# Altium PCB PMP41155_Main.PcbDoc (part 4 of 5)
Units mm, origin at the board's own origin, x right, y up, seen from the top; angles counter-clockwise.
Board outline 74 x 146.5 mm, 8 copper layers (Top Layer, Signal Layer 1, Signal Layer 2, Signal Layer 3, Signal Layer 4, Signal Layer 5, Signal Layer 6, Bottom Layer), stack 1.534 mm thick; 249 components, 190 nets, 902 pads, 747 vias.
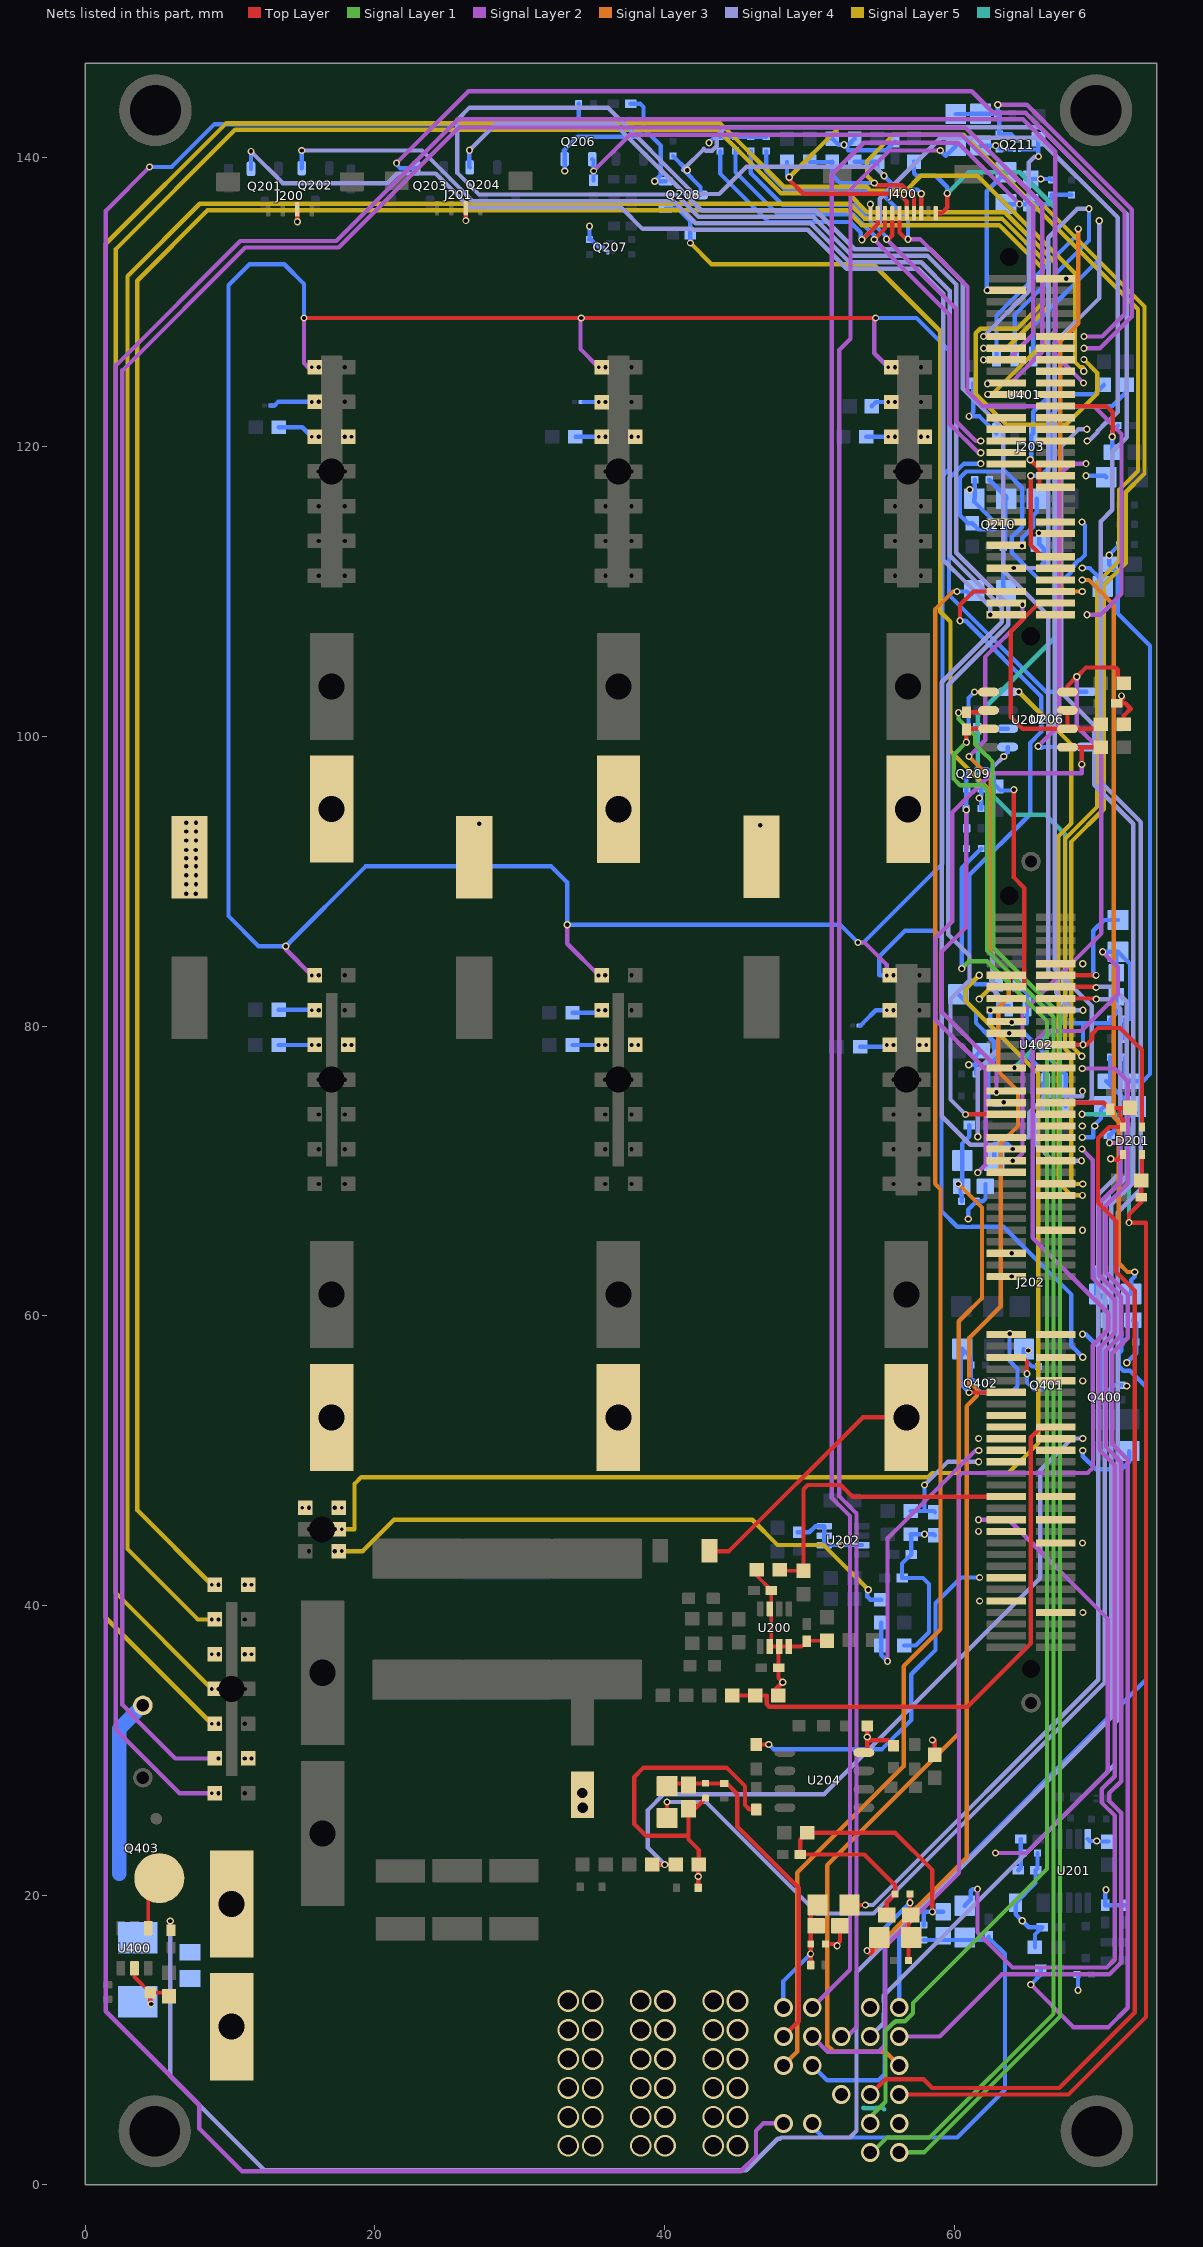
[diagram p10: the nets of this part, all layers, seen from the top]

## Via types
v1: diameter 0.5, hole 0.3, Top Layer to Bottom Layer, 533 vias
v2: diameter 0.508, hole 0.254, Top Layer to Bottom Layer, tented both sides, 102 vias
v3: diameter 1.5, hole 1.2, Top Layer to Bottom Layer, 72 vias
v4: diameter 1.3, hole 0.9, Top Layer to Bottom Layer, 30 vias
v5: diameter 1.27, hole 0.711, Top Layer to Bottom Layer, 6 vias
v6: diameter 1, hole 0.5, Top Layer to Bottom Layer, 2 vias
v7: diameter 2.49, hole 2.49, Top Layer to Bottom Layer, 2 vias

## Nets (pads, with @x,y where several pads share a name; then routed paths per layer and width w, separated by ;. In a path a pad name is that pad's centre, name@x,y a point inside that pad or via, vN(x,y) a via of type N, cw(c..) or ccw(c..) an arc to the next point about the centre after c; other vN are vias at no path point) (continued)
SGND: C202.2 C203.1 C204.2 C205.2 C206.2 C207.2 C208.2 C209.1 C210.2 C212.2 C213.2 C214.2 C215.2 C216.2 C217.2 C218.2 C219.1 C220.2 C221.1 C223.2 C224.2 C225.2 C226.2 C227.2 C228.2 C229.2 C230.1 C231.2 C232.1 C233.2 C234.1 C235.1 C236.1 C300.2 C301.2 C302.2 C306.2 C307.2 C400.1 C401.1 C402.1 C403.1 C404.2 C405.2 C406.2 C407.2 C408.2 C409.2 C410.2 C411.2 C412.2 C413.2 C414.2 C415.2 C416.2 C417.2 C418.2 C419.2 C420.2 C421.1 C422.1 C423.1 C424.1 C425.1 C426.1 D201.1 D201.4 D400.2 J200.2 J201.2 J202.7 J202.10 J202.19 J202.22 J202.35 J202.38 J202.46 J202.47 J202.65 J202.83 J202.97 J202.111 J203.135 J203.157 J203.179 J400.10 pad.1@9.21,36.64 pad.1@11.01,29.44 pad.1@11.01,36.64 pad.1@11.01,41.44 pad.1@15.46,46.76 pad.1@16.12,78.71 pad.1@16.12,120.71 pad.1@17.24,46.76 pad.1@17.92,78.71 pad.1@17.92,120.71 pad.1@35.92,78.71 pad.1@35.924,120.703 pad.1@37.72,78.71 pad.1@37.724,120.703 pad.1@55.81,78.71 pad.1@55.918,120.705 pad.1@57.61,78.71 pad.1@57.718,120.705 pad.2@10.11,10.92 pad.2@17.02,52.99 pad.2@17.02,94.99 pad.2@36.82,52.99 pad.2@36.824,94.983 pad.2@56.71,52.99 pad.2@56.818,94.985 Q206.2 Q207.2 Q208.2 Q209.2 Q210.2 Q211.2 Q400.2 Q401.2 Q402.2 R200.1 R209.1 R216.1 R217.1 R227.1 R228.1 R229.1 R230.2 R247.1 R256.1 R261.1 R267.1 R269.1 R401.1 R403.1 R405.1 R418.1 R419.1 R420.1 R421.1 R430.1 R431.1 R432.1 R443.1 R444.1 R445.1 R456.1 R457.1 R458.1 R459.1 U200.2 U200.3 U200.4 U200.7 U201.8 U202.2 U202.3 U202.4 U202.7 U204.4 U206.2 U207.5 U400.2 U401.4 U402.4 | length 294.5
  Top Layer w0.254: U400.2@3.405,14.96 3.405,14.345 C403.1@4.49,13.26 5.567,13.26 C405.2@5.796,13.031 ; C208.2@46.373,42.468 46.373,42.052 C204.2@47.382,41.043 47.382,37.273 U200.2@47.278,37.168 U200.3@47.928,37.168 ; C205.2@47.878,35.71 47.878,37.118 U200.3@47.928,37.168 ; C206.2@51.221,37.577 49.885,37.577 C207.2@49.83,37.523 49.475,37.168 U200.4@48.578,37.168 U200.3@47.928,37.168
  Top Layer w0.3: C403.1@4.49,13.26 4.49,12.547 v1(4.553,12.485) ; J200.2@14.647,136.406 14.652,136.401 v1(14.652,135.544) ; v1(26.288,135.63) J201.2@26.288,136.454 ; R230.2@42.328,20.511 v1(42.328,21.286) 42.328,22.061 R229.1@42.378,22.111 42.378,23.124 41.658,23.844 41.658,24.1 ; R430.1@42.841,26.7 42.097,25.957 C412.2@41.658,25.957 41.658,24.1 ; C307.2@43.11,43.78 43.13,43.76 44.46,43.76 53.69,52.99 pad.2@56.71,52.99 ; C235.1@46.34,25.914 45.86,25.914 45.86,25.935 45.565,26.23 45.565,27.532 44.288,28.809 38.554,28.809 37.91,28.165 37.91,24.911 38.721,24.1 41.658,24.1 ; R228.1@47.86,33.79 47.61,34.04 47.61,34.15 v1(48.17,34.71) 47.878,35.002 C205.2@47.878,35.71 ; R418.1@51.124,16.631 51.889,16.631 v1@51.92,16.6 ; v1(51.92,16.503) v1@51.92,16.6 ; C407.2@52.117,17.886 52.117,16.797 v1@51.92,16.6 ; U204.4@53.765,29.849 54.01,30.094 v1(54.01,30.919) C221.1@54.01,31.694 ; v1@54.01,30.687 55.447,30.687 C236.1@55.825,30.309 ; C418.2@55.306,18.592 C418.2@55.35,18.636 55.35,19.499 R456.1@55.931,20.08 55.931,20.661 53.788,22.804 C218.2@49.37,22.804 49.37,23.824 C217.2@49.86,24.314 55.926,24.314 58.5,21.74 v1(58.5,18.846) ; C220.2@58.66,29.694 v1@58.66,30.69 ; v1(61.037,54.705) 63.585,54.705 J202.46@63.6,54.72 ; v1(61.405,103.077) U207.5@62.38,103.077 ; v1(65.861,114.058) 66.962,114.058 J203.135@67,114.02 ; J202.97@67,78.72 v1(68.9,78.72) 69.114,78.72 69.124,78.71 69.541,79.127 69.541,79.484 69.93,79.874 71.462,79.874 72.97,78.365 D201.1@72.97,73.04 ; J203.157@67,122.82 70.53,122.82 70.96,122.39 70.96,120.741 v1(70.924,120.705) ; v1(70.82,70.851) 70.92,70.851 70.987,70.783 71.313,70.783 D201.4@71.67,71.14 ; C233.2@71.23,102.3 C233.2@71.563,102.3 ; v1(71.563,102.81) 71.683,102.69 71.563,102.57 C233.2@71.563,102.3 ; R267.1@71.722,100.857 71.722,101.452 72.192,101.922 71.814,102.3 C233.2@71.563,102.3
  Signal Layer 6 w0.3: 53.709,5.322 53.788,5.322 53.818,5.293 54.602,5.293 54.632,5.322 55.068,5.322 55.18,5.21
  Bottom Layer w0.3: C223.2@13.35,78.709 pad.1@15.649,78.709 ; C228.2@13.375,121.366 14.994,121.366 v2(15.65,120.71) ; v1(33.113,139.057) 33.108,139.063 Q206.2@33.108,139.877 33.108,140.41 33.05,140.467 34.013,141.43 37.979,141.43 38.552,142.003 ; C225.2@33.65,78.71 v2(35.45,78.71) ; C227.2@33.854,120.703 v2(35.454,120.703) ; v1(34.823,135.247) 34.823,134.325 R247.1@34.817,134.32 34.93,134.32 35.442,133.807 35.737,133.807 35.894,133.65 35.909,133.65 Q207.2@36.037,133.523 ; C224.2@37.67,143.707 38.32,143.707 38.552,143.475 38.552,142.003 ; Q208.2@40.09,138.35 v1(39.326,138.35) 39.748,138.772 39.748,140.807 38.552,142.003 ; v1(43.07,141.01) 43.49,141.43 C422.1@43.84,141.43 C421.1@45.96,141.43 C424.1@47.02,141.43 ; C213.2@49.188,45.053 49.995,45.053 50.42,45.478 U202.4@51.038,45.478 U202.3@51.038,44.828 U202.2@51.038,44.178 U202.7@53.638,44.178 ; C425.1@51.585,141.29 52.009,140.866 v1(52.401,140.866) ; C426.1@53.145,141.29 52.721,140.866 v1(52.401,140.866) ; C226.2@53.51,78.58 55.21,78.58 v2(55.34,78.71) ; C229.2@53.945,120.703 55.155,120.703 ; R459.1@55.918,141.09 55.318,140.49 52.67,140.49 52.67,140.597 v1(52.401,140.866) ; R227.1@56.558,37.235 57.345,37.235 58.27,38.16 58.27,41.49 57.856,41.904 C212.2@56.405,41.904 56.405,42.898 C215.2@57.035,43.528 57.035,44.898 C214.2@57.005,44.928 58.6,44.928 C216.2@58.675,44.853 ; R457.1@57.901,17.932 57.901,18.701 58.046,18.846 v1(58.5,18.846) C419.2@59.26,18.846 ; R405.1@60.45,57.328 60.45,55.291 v1(61.037,54.705) ; R405.1@60.57,57.328 R405.1@60.57,57.72 ; R405.1@60.72,57.57 R405.1@60.57,57.72 ; v1(60.98,66.69) 60.98,67.348 R445.1@61.542,67.91 61.98,67.91 62.168,68.098 C417.2@62.168,69.11 ; v1(61.01,77.335) 61.515,77.335 ; 61.315,55.57 61.268,55.57 61.17,55.667 C402.1@61.17,56.608 61.17,57.12 R405.1@60.57,57.72 ; C406.2@61.328,124.39 61.328,122.41 v1(61.027,122.11) 61.756,122.11 U401.4@62.926,120.94 ; v1(61.405,103.077) 60.993,102.665 60.993,100.555 C231.2@61.59,100.555 61.595,100.55 U206.2@63.695,100.55 ; C232.1@61.42,117.74 61.42,116.44 R261.1@61.4,116.42 61.4,116.204 Q210.2@62.753,114.851 ; R420.1@61.515,76.71 61.515,77.335 ; Q209.2@61.664,97.211 61.664,97.076 61.88,96.86 61.88,95.905 v1(61.73,95.755) 61.88,95.605 61.88,95.057 R256.1@61.852,95.03 ; R269.1@61.83,140.81 v1(62.871,140.81) 62.901,140.81 C234.1@63.121,140.59 63.171,140.54 64.01,140.54 ; C409.2@61.84,78.31 61.515,77.985 61.515,77.335 ; R403.1@64.82,57.71 64.82,57.065 65.38,56.505 C401.1@65.83,56.505 65.83,55.74 66.04,55.53 ; C414.2@65.3,138.5 v1(65.988,138.5) 66.676,138.5 R432.1@66.736,138.44 ; R209.1@65.584,16.405 65.584,17.283 C210.2@66.079,17.779 65.151,17.779 64.255,18.674 C203.1@64.255,19.475 65.624,20.844 R217.1@65.624,21.715 65.754,21.845 C219.1@65.754,22.905 ; v1@65.884,114.058 C416.2@65.884,113.29 66.198,112.977 R444.1@66.198,111.777 ; C411.2@67.681,82.865 67.681,81.476 U402.4@67.575,81.37 67.575,80.21 68.8,80.21 ; C209.1@68.49,14.53 68.55,14.47 v1(68.55,13.43) ; v1(68.89,50.71) 68.89,50.315 69.785,49.42 71.58,49.42 72.087,49.927 R401.1@72.087,50.665 ; v1@68.901,78.721 68.901,80.11 68.8,80.21 ; U201.8@69.239,23.875 69.409,23.705 69.448,23.745 v1(69.856,23.745) 69.896,23.705 C202.2@70.634,23.705 ; v1@70.524,20.42 v1(70.484,20.38) 70.444,20.34 R200.1@70.444,19.312 R216.1@71.804,19.312 R216.1@71.947,19.312 ; 70.688,54.864 71.03,55.205 C400.1@71.574,55.205 ; C408.2@70.924,119.64 v1(70.924,120.705) 70.924,121.087 R419.1@71.318,121.48 ; C415.2@71.205,82.039 71.205,80.9 R443.1@70.804,80.499 70.804,80.21 68.8,80.21 ; R431.1@71.428,113.26 70.704,112.537 C413.2@70.704,111.897 71.3,111.301 71.3,108.5 73.53,106.27 73.53,76.701 73.037,76.208 C410.2@72.167,76.208 71.81,76.564 R421.1@71.81,77.859 ; v1(71.916,56.759) 72.573,57.415 72.573,59.487 C420.2@72.35,59.71
  other v1: 64.703,18.226 58.5,30.72 68.894,39.523 61.76,40.31 52.198,44.178 68.87,44.32 57.95,44.928 61.68,45.119 61.69,51.529 71.915,55.16 68.88,55.51 65.13,57.61 68.87,65.92 68.841,73.107 68.89,84.32 6.98,89.146 7.64,89.146 6.98,89.806 7.65,89.806 6.98,90.426 7.65,90.426 6.98,91.036 7.65,91.036 6.99,91.59 7.65,91.59 6.98,92.17 7.64,92.17 6.98,92.83 7.65,92.83 6.98,93.45 7.65,93.45 46.61,93.87 27.21,93.99 6.98,94.06 7.65,94.06 70.713,112.529 61.079,117.038 67.74,131.62 54.221,136.761
  other v2: 11.48,29.44 8.74,36.64 11.48,36.64 11.49,41.44 14.98,46.76 17.72,46.76 15.65,78.71 18.39,78.71 38.19,78.71 58.08,78.71 38.194,120.703 18.39,120.71 55.448,120.705 58.188,120.705
  other v3: 33.36,2.69 35.04,2.69 38.36,2.69 40.04,2.69 43.36,2.69 45.04,2.69 33.36,4.69 35.04,4.69 38.36,4.69 40.04,4.69 43.36,4.69 45.04,4.69 33.36,6.69 35.04,6.69 38.36,6.69 40.04,6.69 43.36,6.69 45.04,6.69 33.36,8.69 35.04,8.69 38.36,8.69 40.04,8.69 43.36,8.69 45.04,8.69 33.36,10.69 35.04,10.69 38.36,10.69 40.04,10.69 43.36,10.69 45.04,10.69 33.36,12.69 35.04,12.69 38.36,12.69 40.04,12.69 43.36,12.69 45.04,12.69
  other v4: 56.21,4.24 52.21,6.24 54.21,12.24
  other v5: 34.35,26.04 34.32,27.05
SHELF_ADDR0: C407.1 R408.1 R414.2 R418.2 | length 8.8
  Top Layer w0.3: R408.1@50.101,15.181 50.101,18.856 R414.2@50.571,19.326
  Bottom Layer w0.3: v4(48.21,12.24) 48.21,14.064 v1(50.09,15.944)
SHELF_ADDR1: C412.1 R422.1 R425.2 R430.2 | length 24.2
  Top Layer w0.3: R425.2@40.178,27.532 40.353,27.708 42.841,27.708 R422.1@44.139,27.708 44.314,27.708 45.03,26.991 45.03,24.744 49.263,20.512 49.263,12.632 49.263,11.953 49.263,11.293 v4(48.21,10.24)
SHELF_ADDR2: C415.1 R437.1 R440.2 R443.2 | length 108.3
  Signal Layer 2 w0.3: v4(50.21,10.24) 51.26,9.19 54.8,9.19 55.25,9.64 55.25,16.457 60.334,21.54 60.334,48.931 60.551,49.148 62.752,49.148 69.218,49.148 69.589,49.519 69.589,54.181 69.578,54.192 69.578,56.128 69.58,56.13 69.58,57.978 70.643,59.041 70.643,60.178 65.435,65.386 65.435,72.04 65.435,78.769 66.336,79.67 68.78,79.67 71.29,82.18 71.29,84.105 v1(70.255,85.14)
  Bottom Layer w0.3: v1(70.255,85.14) R440.2@71.32,85.14 ; C415.1@71.205,83.691 71.205,85.025 R440.2@71.32,85.14 ; R437.1@71.79,79.16 R443.2@71.79,80.499 ; R443.2@71.829,80.499 72.168,80.499 72.168,84.292 72.014,84.446 R440.2@71.32,85.14
SHELF_ADDR3: C420.1 R451.1 R455.2 R458.2 | length 59.7
  Bottom Layer w0.3: v4(56.21,12.24) 56.21,17.83 57.354,18.974 57.354,19.073 57.675,19.393 57.773,19.393 73.25,34.87 73.25,55.104 72.143,56.211 71.69,56.211 71.369,56.532 71.369,57.417 71.535,57.583 R458.2@71.535,58.19 71.535,58.873 C420.1@70.698,59.71 ; R455.2@69.805,61.51 R451.1@69.805,63.185 ; R455.2@70.03,61.51 70.454,61.086 C420.1@70.454,59.71
SYS_AC_LOSS_1: C419.1 R450.1 R454.2 R457.2 | length 35.1
  Bottom Layer w0.3: v4(50.21,4.24) 50.21,4.03 50.97,3.27 60.21,3.27 63.51,6.57 63.51,15.95 62.553,16.907 R457.2@57.901,16.907 59.26,16.907 60.731,16.907 62.169,16.907 R450.1@62.381,17.12
SYS_AC_LOSS_2: C417.1 R438.1 R442.2 R445.2 | length 76.1
  Signal Layer 3 w0.3: v4(56.21,8.24) 55.25,9.2 51.686,9.2 51.579,9.308 51.23,9.657 51.23,22.069 60.323,31.163 60.323,59.624 61.925,61.226 61.925,67.479 v1(60.295,69.11)
  Bottom Layer w0.3: v1(60.295,69.11) 60.295,68.95 C417.1@60.514,68.95 ; R445.2@60.517,67.91 60.517,68.34 60.436,68.421 60.436,68.872 C417.1@60.514,68.95 ; R438.1@61.037,73.18 61.037,72.367 60.567,71.897 R442.2@60.567,70.72 60.567,69.003 C417.1@60.514,68.95
SYS_BBU_ALERT: Q206.3 R239.1 | length 215.7
  Signal Layer 2 w0.3: v1@4.55,139.43 1.42,136.3 1.42,11.98 7.872,5.528 7.872,3.888 10.825,0.935 45.265,0.935 46.32,1.99 46.32,3.739 46.821,4.24 v4(48.21,4.24)
  Bottom Layer w0.3: v1(4.446,139.326) 5.966,139.326 8.935,142.295 34.075,142.295 R239.1@34.075,143.707
SYS_BBU_RESET: C418.1 R452.1 R453.2 R456.2 | length 22.8
  Top Layer w0.3: R452.1@56.848,15.491 C418.1@56.848,18.636 ; R456.2@56.956,20.08 56.956,18.681 C418.1@57.001,18.636
  Bottom Layer w0.3: v4(50.21,8.24) 51.23,7.22 54.8,7.22 55.21,7.63 55.21,17.725 v1(56.955,19.47)
SYS_PLS_LOP: Q208.3 R246.1 | length 174.1
  Signal Layer 4 w0.3: 41.29,139.15 42.723,140.583 42.843,140.463 43.297,140.463 43.617,140.783 43.617,141.237 43.497,141.357 44.22,142.08 65.937,142.08 71.93,136.087 71.93,120.67 70.924,119.664 70.924,115.664 70.12,114.86 70.12,96.857 72.88,94.097 72.88,68.743 71.299,67.162 71.299,32.087 71.11,31.897 71.11,29.045 55.142,13.078 55.142,12.647 55.157,12.632 55.157,11.848 55.142,11.833 55.142,11.172 v4(54.21,10.24)
  Bottom Layer w0.3: R246.1@40.59,140.085 41.568,139.107 v1(41.58,139.107) ; 41.29,139.15 42.49,137.95 Q208.3@42.49,137.4
SYS_Present_L: C414.1 R424.1 R427.2 R432.2 | length 149
  Signal Layer 2 w0.3: v4(50.21,12.24) 52.815,14.845 52.815,46.177 51.54,47.453 51.54,138.79 53.76,141.01 58.819,141.01 58.823,141.015 59.277,141.015 59.281,141.01 60.27,141.01 v1(64.51,136.77)
  Bottom Layer w0.3: R427.2@63.575,136.77 C414.1@65.3,136.77 ; C414.1@65.3,136.848 65.742,136.848 65.829,136.761 66.649,136.761 66.736,136.848 R432.2@66.736,137.415 68.093,137.415 R424.1@68.11,137.398
SYS_PULSE_MGMT_1: C410.1 R411.1 R417.2 R421.2 | length 84.7
  Signal Layer 2 w0.3: v4(56.21,10.24) 59.005,10.24 63.295,14.53 70.714,14.53 71.538,15.354 71.538,25.298 71.538,25.678 71.062,26.154 70.714,26.502 70.714,27.047 71.538,27.871 71.538,49.889 70.483,50.944 70.483,54.552 70.473,54.563 70.473,55.757 70.474,55.759 70.474,57.607 71.538,58.671 71.538,61.291 70.025,62.804 70.025,67.786 71.468,69.229 71.468,71.953 v1(70.726,71.953)
  Bottom Layer w0.3: C410.1@70.515,76.208 R417.2@72.225,74.498 ; R411.1@70.69,72.413 R411.1@70.716,72.439 ; R411.1@70.716,72.503 R411.1@70.716,72.439 ; v1(70.726,71.953) 70.716,71.963 R411.1@70.716,72.439 ; C410.1@70.785,76.208 R421.2@70.785,77.859 ; R417.2@72.56,74.033 72.31,74.033 R411.1@70.716,72.439
SYS_RS485+: R264.2 U207.6 | length 110.1
  Top Layer w0.3: v1(60.3,101.65) 60.81,101.65 R264.2@60.85,101.69 62.263,101.69 U207.6@62.38,101.807
  Signal Layer 1 w0.3: v4(56.21,2.24) 57.926,2.24 67.312,11.626 67.312,80.828 62.723,85.417 62.723,95.342 62.725,95.343 62.725,96.167 62.723,96.168 62.723,96.515 62.65,96.588 62.65,98.283 62.262,98.671 62.246,98.671 61.925,98.992 61.445,99.472 61.445,100.071 60.3,101.216 v1(60.3,101.65)
SYS_RS485-: R264.1 U207.7 | length 111
  Top Layer w0.3: v1(60.85,99.618) R264.1@60.85,100.49 60.9,100.54 62.283,100.54 62.333,100.49 U207.7@62.38,100.537
  Signal Layer 1 w0.3: v4(54.21,2.24) 54.338,2.24 55.368,3.27 58.324,3.27 66.858,11.805 66.858,80.649 62.276,85.231 62.276,95.527 62.277,95.528 62.277,95.982 62.276,95.983 62.276,96.33 61.976,96.63 60.424,96.63 59.984,97.069 59.984,98.752 v1(60.85,99.618)
SYS_SOH_L: R260.2 | length 108.6
  Signal Layer 3 w0.3: v4(48.21,8.24) 49.157,9.187 49.157,21.551 56.513,28.906 56.513,35.813 59.065,38.365 59.065,68.748 58.69,69.124 58.69,108.785 59.925,110.02 v1(60.197,110.02)
  Bottom Layer w0.3: v1(60.197,110.02) 60.89,110.02 61.11,109.8 R260.2@61.39,110.08
SYS_SYNC_START2_L: R253.1 | length 98.2
  Signal Layer 1 w0.3: v4(54.21,4.24) 54.21,4.682 55.263,5.735 55.263,9.746 55.263,10.589 55.263,10.632 55.818,11.187 55.861,11.187 55.966,11.293 56.602,11.293 57.157,11.848 57.157,12.558 66.411,21.812 66.411,80.354 64.499,82.266 62.276,84.489 61.029,84.489 v1(60.52,83.98)
  Bottom Layer w0.3: v1(60.52,83.98) 60.52,90.918 R253.1@61.872,92.27
SYS_SYNC_START_L: R268.2 | length 137.8
  Signal Layer 2 w0.3: v4(52.21,10.24) 52.615,10.24 53.263,10.888 53.263,14.66 53.263,46.363 52.815,46.81 52.198,47.428 52.063,47.563 52.063,110.615 52.063,126.692 52.848,127.478 52.848,134.162 52.848,137.775 55.017,139.944 55.541,140.467 v1(59.05,140.467)
  Bottom Layer w0.3: v1(59.05,140.467) 59.419,140.099 R268.2@60.11,140.79
UC_AD_BBU_ISHARE: C219.2 J202.24 R215.2 R217.2 | length 36.6
  Signal Layer 2 w0.3: v1(61.68,45.92) 63.77,45.92 70.62,39.07 70.62,28.526 65.004,22.91 v1(62.86,22.91)
  Bottom Layer w0.3: v1(62.86,22.91) 64.589,22.91 64.674,22.825 C219.2@64.754,22.905 ; R217.2@64.424,21.715 64.604,21.895 64.604,22.825 64.604,22.905 R215.2@64.604,23.875
UC_AD_ICS_1ph: pad.1@16.12,81.11 R235.1 | length 2.3
  Bottom Layer w0.3: R235.1@13.35,81.13 pad.1@15.65,81.13
  other v2: 15.65,81.11
UC_AD_ICS_2ph: pad.1@35.92,81.11 R237.1 | length 1.9
  Bottom Layer w0.3: R237.1@33.65,80.94 35.28,80.94 v2(35.45,81.11)
UC_AD_ICS_3ph: pad.1@55.81,81.11 R238.2 | length 2.3
  Bottom Layer w0.3: R238.2@53.528,80.041 53.74,80.253 53.74,80.26 54.59,81.11 v2(55.34,81.11)
UC_AD_ICS_4ph: pad.1@55.918,123.105 R243.1 | length 1.3
  Bottom Layer w0.3: R243.1@54.315,122.82 54.6,123.105 v2(55.448,123.105)
UC_AD_ICS_5ph: pad.1@35.924,123.103 R240.2 | length 1
  Bottom Layer w0.3: 34.425,123.103 v2(35.454,123.103)
UC_AD_ICS_6ph: pad.1@16.12,123.11 R242.2 | length 2.9
  Bottom Layer w0.3: R242.2@12.855,122.843 13.053,122.843 13.32,123.11 v2(15.65,123.11)
UC_AD_NTC_AMB_IN: J202.40
UC_AD_NTC_AMB_OUT: J202.42
UC_AD_NTC_HS_1: J202.23
UC_AD_NTC_HS_2: J202.27
UC_AD_Total_Charge_Current_Vbattery: C216.1 J202.34 R212.2 | length 7.9
  Signal Layer 4 w0.3: v1(57.95,48.32) 59.55,49.92 v1(61.69,49.92)
  Bottom Layer w0.3: R212.2@57.005,46.528 57.95,46.528 ; v1(57.95,48.32) 57.95,46.528 ; C216.1@58.675,46.453 58.6,46.528 57.95,46.528
UC_AD_Total_Discharge_Current_Vbus: C208.1 J202.28 R205.2 | length 21.7
  Top Layer w0.254: C208.1@47.973,42.468 48.048,42.393 R205.2@49.605,42.393
  Top Layer w0.3: R205.2@49.605,42.393 49.605,48.033 49.892,48.32 52.168,48.32 52.968,47.52 J202.28@63.6,47.52
UC_AD_VBAT_SENSE: J202.36 R224.1 R227.2 | length 20.1
  Signal Layer 2 w0.3: v1(55.405,36.156) 55.405,44.635 61.48,50.71 v1(61.7,50.71)
  Bottom Layer w0.3: R224.1@54.958,38.82 54.958,36.603 v1(55.405,36.156)
UC_AD_VORING: J202.37 R226.1 R229.2 | length 51.1
  Top Layer w0.3: R226.1@38.923,22.11 v1(40.028,22.11) R229.2@40.777,22.11
  Signal Layer 4 w0.3: v1(40.028,22.11) 38.857,23.28 38.857,25.886 39.951,26.98 51.033,26.98 65.95,41.897 65.95,49.348 68.131,51.529 v1(68.89,51.529)
UC_AD_VORING1: J202.39 R225.1 R228.2 | length 39.3
  Top Layer w0.3: R225.1@44.68,33.79 R228.2@46.26,33.79 47.063,33.79 47.063,33.192 47.237,33.018 48.483,33.018 60.928,33.018 65.3,37.39 65.3,51.62 65.89,52.21 66.89,52.21 J202.39@67,52.32
UC_BBU_ISHARE_PWM: J202.93 R208.1 | length 79.4
  Signal Layer 2 w0.3: v1(65.3,13.825) 68.233,10.892 70.654,10.892 71.985,12.223 71.985,50.075 70.931,51.129 70.931,54.737 70.92,54.748 70.92,55.572 70.922,55.574 70.922,57.422 71.985,58.485 71.985,61.477 70.473,62.989 70.473,67.601 71.985,69.113 71.985,76.191 71.096,77.08 v1(68.85,77.08)
  Bottom Layer w0.3: v1(65.3,13.825) 65.974,14.499 R208.1@65.974,14.925
UC_BMS_AUX_DIR: C421.2 J203.152 J400.7 | length 31.9
  Top Layer w0.3: v1@55.334,134.224 55.73,134.62 J400.7@55.73,136.13
  Signal Layer 2 w0.3: v1(55.33,134.34) 60.15,129.52 60.15,121.753 61.491,120.411 v1(61.846,120.411)
  Bottom Layer w0.3: C421.2@45.96,140.43 45.96,138.91 48.16,136.71 53.129,136.71 55.334,134.505 v1@55.334,134.224
UC_BMS_AUX_ON: J202.95 J400.5 R446.1 | length 96.1
  Top Layer w0.3: v1(48.61,138.62) 48.605,138.615 48.605,138.465 49.58,137.49 56.185,137.49 56.73,136.945 J400.5@56.73,136.13
  Signal Layer 5 w0.3: v1(48.61,138.62) 52.024,142.034 60.816,142.034 73.15,129.7 73.15,118.164 71.859,116.873 71.859,111.979 71.563,111.683 70.34,110.46 70.34,94.99 68.1,92.75 68.1,78.63 v1(68.81,77.92)
  Bottom Layer w0.3: R446.1@48.465,139.68 48.465,138.765 v1(48.61,138.62)
UC_BMS_CHG_EN: C422.2 J203.151 J400.9 | length 56.1
  Top Layer w0.3: v1(53.633,134.311) 53.633,134.36 53.696,134.36 54.73,135.394 J400.9@54.73,136.13
  Signal Layer 4 w0.3: v1(53.633,134.311) 53.633,134.36 53.696,134.36 54.86,135.524 54.86,137.139 59.078,141.357 62.644,141.357 63.098,141.357 65.778,141.357 71.3,135.835 71.3,122.415 70.585,121.699 70.512,121.699 69.93,121.117 69.93,121.044 69.379,120.494 69.237,120.494 v1@69.167,120.424
  Bottom Layer w0.3: C422.2@43.84,140.43 43.84,138.88 47.19,135.53 52.832,135.53 53.56,134.802 53.56,134.36 53.609,134.311 v1(53.633,134.311)
  other v1: 69.184,120.407
UC_BMS_DCH_EN: C423.2 J203.150 J400.8 | length 33.1
  Top Layer w0.3: v1(54.48,134.33) 55.23,135.08 J400.8@55.23,136.13
  Signal Layer 2 w0.3: v1(54.48,134.33) 59.703,129.107 59.703,121.567 59.72,121.55 v1@61.675,119.595
  Bottom Layer w0.3: C423.2@44.9,140.45 44.9,138.98 47.8,136.08 53.01,136.08 54.48,134.61 v1@54.48,134.224
  other v1: 61.846,119.595
UC_BMS_FAULT: C424.2 J203.121 J400.6 | length 54.7
  Top Layer w0.3: J400.6@56.23,136.13 56.23,134.812 v1@56.818,134.224
  Signal Layer 2 w0.3: v1(56.82,134.35) 57.645,134.35 60.927,131.068 60.927,123.85 61.958,122.82 69.64,122.82 71.563,120.897 71.563,118.635 71.563,109.863 70.12,108.42 v1(69.18,108.42)
  Bottom Layer w0.3: C424.2@47.02,140.43 47.02,139.07 48.416,137.674 54.836,137.674 56.818,135.692 v1@56.818,134.224
UC_BMS_PACK_ON: J202.94 J400.1 R449.1 | length 81.9
  Top Layer w0.3: J400.1@58.73,136.13 59.121,136.13 59.53,136.539 v1(59.53,137.51)
  Signal Layer 6 w0.3: v1(59.53,137.51) 60.99,138.97 64.527,138.97 66.95,136.547 66.95,106.823 63.292,103.166 61.632,101.505 61.632,96.974 63.999,94.607 66.313,94.607 67.75,93.17 67.681,93.101 67.681,80.646 v1(64.173,77.138)
  Bottom Layer w0.3: R449.1@57.23,139.71 57.23,138.9 57.403,138.727 58.73,138.727 59.53,137.927 v1(59.53,137.51)
UC_BMS_SCL: C425.2 J202.73 J400.4 R447.1 | length 99.4
  Top Layer w0.3: v1(54.48,138.23) 54.63,138.08 56.407,138.08 57.23,137.257 J400.4@57.23,136.13
  Signal Layer 5 w0.3: v1(54.48,138.23) 53.98,138.73 53.98,139.75 55.78,141.55 60.667,141.55 72.703,129.515 72.703,118.349 71.411,117.058 71.411,116.738 71.411,112.164 69.893,110.646 69.893,95.175 67.653,92.935 67.653,92.604 67.653,78.445 68.1,77.998 68.1,69.39 68.38,69.11 v1(68.89,69.11)
  Bottom Layer w0.3: R447.1@50.025,139.68 51.575,139.68 C425.2@51.585,139.69 51.585,138.772 52.127,138.23 v1(54.48,138.23)
UC_BMS_SDA: C426.2 J202.86 J400.3 R448.1 | length 146.7
  Top Layer w0.3: J400.3@57.73,136.13 v1(57.73,137.49) ; v1(60.783,73.91) 60.793,73.92 J202.86@63.6,73.92
  Signal Layer 4 w0.3: v1(55.155,138.73) 54.535,139.35 45.66,139.35 43.78,137.47 42.04,137.47 36.078,143.432 26.542,143.432 25.7,142.59 25.7,138.921 27.188,137.433 40.812,137.433 42.165,136.08 42.351,135.893 50.262,135.893 52.953,133.203 58.16,133.203 60.15,131.213 60.15,128.865 60.15,112.693 63.74,109.103 63.74,108.912 63.74,108.349 63.74,107.717 59.597,103.574 59.597,86.331 61.067,84.861 61.067,83.753 61.067,83.177 59.747,81.857 59.747,74.946 v1(60.783,73.91)
  Bottom Layer w0.3: C426.2@53.145,139.69 R448.1@54.705,139.69 54.705,139.18 v1(55.155,138.73) 56.128,137.757 57.463,137.757 v1(57.73,137.49)
UC_CAN_EN: J203.148 U206.5 | length 22.9
  Bottom Layer w0.3: v1(61.846,118.852) 61.846,118.85 60.679,118.85 59.65,117.821 59.65,109.78 66.34,103.09 U206.5@69.145,103.09
UC_CAN_STBY: J203.147 U206.8 | length 24.9
  Signal Layer 2 w0.3: v1(65.8,99.336) 67.25,100.786 67.25,118.02 68.082,118.852 v1(69.11,118.852)
  Bottom Layer w0.3: v1(65.8,99.336) 65.895,99.24 66.05,99.24 66.09,99.28 U206.8@69.145,99.28
UC_COMP_CHG: J202.62
  other v1: 63.99,64.324
UC_COMP_DIR: J202.55 Q400.1 | length 4.5
  Bottom Layer w0.3: v1(68.87,58.73) 69.087,58.73 70.142,57.675 70.142,54.905
UC_COMP_DIR_AUX: J203.162 pad.1@9.21,29.44 | length 187.4
  Signal Layer 2 w0.3: pad.1@8.73,29.44 8.262,29.44 6.214,29.44 3.22,32.434 3.22,32.495 2.567,33.148 2.567,125.287 11.053,133.773 17.203,133.773 17.515,133.773 25.803,142.06 60.79,142.06 66.09,136.76 66.09,126.575 63.931,124.415 v1@62.331,124.415
  other v1: 62.304,124.361
UC_COMP_DIR_CHG: J203.156
UC_EEPROM_CLK: J202.104 R434.1 U402.6 | length 8.5
  Bottom Layer w0.3: v1@62.5,81.11 62.5,80.041 63.261,79.28 64.682,77.859 65.176,77.859 66.305,76.73 U402.6@66.305,76.07 ; R434.1@66.16,74.448 66.16,74.878 U402.6@66.16,76.07
  other v1: 62.505,81.099
UC_EEPROM_SIMO: J202.100 R433.1 U402.5 | length 7.3
  Bottom Layer w0.3: v1@63.81,79.53 64.85,79.53 67.7,76.68 67.7,76.07 R433.1@67.7,74.483 ; R433.1@67.699,74.483 R433.1@67.699,74.545
  other v1: 63.808,79.506
UC_EEPROM_SOMI: J202.102 R436.1 U402.2 | length 4
  Bottom Layer w0.3: v1(63.99,80.273) 63.999,80.281 64.07,80.21 65.035,80.21 U402.2@65.035,81.37 65.035,82.264 64.73,82.569 64.73,82.673 R436.1@64.508,82.895
UC_EEPROM_STE: J203.126 R429.1 U402.1 | length 38
  Top Layer w0.3: v1(60.411,107.995) 60.411,109.101 61.33,110.02 J203.126@63.6,110.02
  Bottom Layer w0.3: v1(60.411,107.995) 60.802,107.995 66.008,102.79 66.008,100.317 65.253,99.562 65.253,99.109 65.253,94.643 61.067,90.457 61.067,83.303 61.475,82.895 R429.1@62.885,82.895 62.885,81.905 63.42,81.37 U402.1@63.765,81.37
UC_En_Disable: J202.51 pad.1@16.12,83.51 pad.1@16.12,125.51 pad.1@35.92,83.51 pad.1@35.924,125.503 pad.1@55.81,83.51 pad.1@55.918,125.505 | length 256
  Top Layer w0.3: v1(15.112,128.91) v1(34.26,128.91) v1(54.58,128.91)
  Signal Layer 2 w0.3: v1(13.85,85.53) 13.85,85.31 v2(15.65,83.51) ; v1(15.112,128.91) 15.112,125.792 15.394,125.51 v2(15.65,125.51) ; v1(33.29,87.013) 33.29,85.7 pad.1@35.48,83.51 ; v1(34.26,128.91) 34.2,128.85 34.2,126.757 v2(35.454,125.503) ; v1(53.36,85.78) 53.82,85.78 55.34,84.26 v2(55.34,83.51) ; v1(54.58,128.91) 54.48,128.81 54.48,126.473 v2(55.448,125.505)
  Bottom Layer w0.3: v1(15.112,128.91) 15.112,131.258 13.748,132.622 11.352,132.622 9.891,131.161 9.891,87.609 11.97,85.53 v1(13.85,85.53) 19.356,91.036 32.187,91.036 33.29,89.933 v1(33.29,87.013) ; v1@33.286,87.016 52.124,87.016 v1(53.36,85.78) 53.74,85.78 59.203,91.243 59.203,118.006 59.65,118.453 59.65,126.657 57.397,128.91 v1(54.58,128.91) ; v2(55.34,83.51) 54.828,83.51 54.828,84.808 56.613,86.594 58.676,86.594 59.13,86.14 59.13,67.243 60.223,66.15 60.746,66.15 60.753,66.143 61.207,66.143 61.214,66.15 63.42,66.15 68.1,61.47 68.1,57.937 v1(68.887,57.15)
  other v2: 35.45,83.51
UC_En_Disable_AUX: J203.160 pad.1@9.21,34.24 | length 185.5
  Signal Layer 5 w0.3: v2(8.74,34.24) 2.12,40.86 2.12,133.67 10.363,141.913 42.941,141.913 43.645,141.913 48.045,137.513 48.677,137.513 52.695,137.513 53.994,136.213 54.447,136.213 63.494,136.213 66.98,132.727 66.98,127.98 62.59,123.59 62.37,123.59 v1(62.33,123.63)
UC_En_Disable_CHG: J203.154
UC_FAN_CLK: J203.165 pad.1@9.21,41.44 | length 183.3
  Signal Layer 5 w0.3: v2(8.74,41.44) 3.59,46.59 3.59,131.48 8.451,136.341 52.601,136.341 53.623,135.319 63.123,135.319 66.085,132.357 66.085,129.904 64.35,128.169 61.803,128.169 61.483,127.849 61.483,127.395 61.483,126.247 61.483,124.157 61.483,123.668 63.621,121.53 67.735,121.53 69.89,123.685 69.89,125.11 v1(68.96,126.04)
UC_FAN_PWM: J203.168 pad.1@9.21,39.04 | length 171.7
  Signal Layer 5 w0.3: v2(8.74,39.04) 7.784,39.04 2.92,43.904 2.92,131.79 7.918,136.788 52.787,136.788 53.809,135.766 63.309,135.766 66.533,132.542 66.533,129.719 63.628,126.814 v1(62.036,126.814)
UC_FB_DIR: J202.52 Q401.1 | length 4.3
  Top Layer w0.3: J202.52@63.6,57.12 64.765,57.12 65.035,56.85 v1(65.035,56.01)
  Bottom Layer w0.3: v1(65.035,56.01) 65.035,55.421 65.531,54.925 66.106,54.925
UC_LED_BBU_OK: J203.122 Q201.1 | length 77.2
  Signal Layer 4 w0.3: v1(11.447,140.41) 13.654,138.203 16.441,138.203 20.877,138.203 21.554,138.88 24.207,138.88 26.549,136.538 27.182,136.538 37.011,136.538 38.493,135.057 41.923,135.057 41.981,134.999 49.892,134.999 51.241,133.65 52.583,132.308 57.539,132.308 59.255,130.592 59.255,112.195 60.883,110.567 62.5,108.95 v1(62.5,108.422)
  Bottom Layer w0.3: Q201.1@11.447,139.201 v1(11.447,140.41)
UC_LED_EOL: J203.169 Q203.1 | length 67.9
  Signal Layer 2 w0.3: v1(21.5,139.6) 26.46,144.56 61.22,144.56 62.7,143.08 62.781,143.08 62.783,143.078 63.237,143.078 63.239,143.08 64.937,143.08 71.77,136.247 71.77,129.17 70.222,127.622 v1(68.971,127.622)
  Bottom Layer w0.3: v1(21.5,139.6) 21.5,139.5 21.747,139.253 Q203.1@22.863,139.253
UC_LED_FAIL: J202.103 Q204.1 | length 94.6
  Signal Layer 4 w0.3: v1(26.536,140.489) 28.334,142.287 36.59,142.287 42.537,136.341 50.448,136.341 53.138,133.65 58.345,133.65 60.597,131.398 60.597,124.03 63.403,121.225 63.403,115.047 63.403,114.593 63.403,111.453 66.503,108.353 66.503,106.676 66.503,83.78 67.057,83.225 67.057,82.303 68.25,81.11 v1(68.901,81.11)
  Bottom Layer w0.3: v1@26.53,140.5 26.53,139.326 Q204.1@26.548,139.308
UC_LED_LOW_V: J202.89 Q202.1 | length 123.4
  Signal Layer 4 w0.3: v1(14.95,140.467) 23.253,140.467 24.393,139.327 25.253,138.467 26.734,136.986 40.627,136.986 42.166,135.446 50.077,135.446 51.443,134.08 52.768,132.755 57.725,132.755 59.703,130.777 59.703,128.68 59.703,112.507 63.292,108.918 63.292,107.902 59.15,103.76 59.15,73.783 61.111,71.823 62.985,71.823 63.5,72.338 65.17,72.338 65.17,74.028 66.31,75.167 68.86,75.167 v1(68.86,75.52)
  Bottom Layer w0.3: Q202.1@14.95,139.255 v1(14.95,140.467)
UC_MODE: J202.56 Q402.1 | length 7.1
  Bottom Layer w0.3: 61.542,55.022 61.855,54.71 63.95,54.71 64.382,55.141 64.382,56.337 63.823,56.896 63.823,58.524 63.947,58.648 v1(63.834,58.761)
UC_MODE_AUX: J203.163 pad.1@9.21,31.84 | length 187.9
  Signal Layer 5 w0.3: v2(8.74,31.84) 1.42,39.16 1.42,134.03 9.75,142.36 43.83,142.36 48.23,137.96 53.976,137.96 54.253,137.683 56.656,137.683 57.701,138.727 61.613,138.727 68.35,131.99 68.35,125.876 68.733,125.493 68.875,125.493 68.953,125.414 v1(68.953,125.225)
UC_MODE_CHG: J203.159
UC_ORING_AUX: J203.153 R407.1 | length 191.1
  Top Layer w0.3: v1(5.88,18.22) 5.92,18.18 R407.1@5.92,17.57
  Signal Layer 4 w0.3: v1(5.88,18.22) 5.88,8.71 5.88,7.52 12.388,1.012 45.642,1.012 47.263,2.632 47.818,3.187 47.978,3.187 48.061,3.27 52.794,3.27 53.263,3.738 53.263,7.645 53.263,9.875 53.263,10.632 53.263,11.848 53.263,14.683 70.852,32.272 70.852,42.874 70.852,60.128 70.852,67.69 72.363,69.2 72.363,93.982 69.673,96.672 69.673,100.762 67.397,103.038 67.397,120.032 68.58,121.215 v1(69.169,121.215)
UC_ORING_EN: J202.110 pad.1@17.24,45.26 | length 87.2
  Signal Layer 5 w0.3: v2(17.72,45.26) 18.594,45.26 18.594,48.4 19.061,48.867 58.177,48.867 58.192,48.852 58.488,49.148 63.738,49.148 65.82,51.23 65.82,76.721 60.783,81.758 60.783,82.624 60.834,82.624 v1(61.73,83.52)
UC_RS485_DIR: J203.123 R267.2 U207.2 U207.3 | length 17.8
  Top Layer w0.3: J203.123@67,109.22 65.87,109.22 63.921,107.271 63.921,103.317 63.921,102.863 63.921,101.339 64.723,100.537 U207.2@67.83,100.537 ; U207.3@67.83,101.807 U207.2@67.83,100.537 ; R267.2@70.122,100.857 69.802,100.537 U207.2@67.83,100.537
UC_SYS_AC_LOSS_1: J202.79 R454.1 | length 74
  Signal Layer 2 w0.3: v1(61.61,20.42) 61.61,17.43 64.035,15.005 70.557,15.005 71.091,15.539 71.091,25.493 70.186,26.397 70.186,27.312 71.091,28.216 71.091,49.704 70.036,50.759 70.036,54.367 70.025,54.377 70.025,55.943 70.027,55.944 70.027,57.792 71.091,58.856 71.091,61.106 69.578,62.619 69.578,67.971 69.578,70.763 v1(68.822,71.519)
  Bottom Layer w0.3: R454.1@60.731,19.278 61.15,19.697 61.15,20.3 61.27,20.42 v1(61.61,20.42)
UC_SYS_AC_LOSS_2: J202.80 R442.1 | length 2.6
  Bottom Layer w0.3: R442.1@62.767,70.72 62.767,71.891 63.675,71.891 v1(64.047,71.519)
UC_SYS_BBU_A0: J203.145 R415.1 | length 1.4
  Bottom Layer w0.3: v1(69.11,118.02) 70.39,118.02 R415.1@70.5,117.91
UC_SYS_BBU_A1: J203.129 R426.1 | length 2.2
  Bottom Layer w0.3: v1(68.84,111.645) 69.355,111.645 70.03,110.97 70.03,110.587 R426.1@70.255,110.362
UC_SYS_BBU_A2: J203.134 R441.1 | length 4.7
  Top Layer w0.3: J203.134@63.6,113.22 63.661,113.159 v1(64.688,113.159)
  Bottom Layer w0.3: v1@64.703,113.26 64.703,113.723 65.466,114.486 65.466,115.27 65.7,115.504 R441.1@65.7,116.42
UC_SYS_BBU_ALERT: J203.166 Q206.1 R241.1 | length 47.9
  Signal Layer 2 w0.3: v1(35.106,139.057) 37.599,141.55 42.836,141.55 42.843,141.557 43.297,141.557 43.304,141.55 46.454,141.55 60.51,141.55 63.003,139.057 65.466,136.594 65.466,127.776 63.7,126.01 62.04,126.01 v1(62.03,126.02)
  Bottom Layer w0.3: Q206.1@35.007,139.877 35.1,139.785 R241.1@35.1,138.412
UC_SYS_BBU_RESET_H: J203.124 R453.1 | length 104.6
  Top Layer w0.3: v1(53.98,16.174) 54.21,15.944 54.348,16.082 54.348,17.086 R453.1@54.836,17.086 ; J203.124@63.6,109.22 64.605,109.22 v1(64.723,109.101)
  Signal Layer 2 w0.3: v1@61.157,98.765 62.14,99.748 62.14,105.49 64.723,108.073 v1(64.723,109.101)
  Signal Layer 3 w0.3: v1(53.98,16.174) 54.433,16.174 57.182,18.923 57.502,19.243 60.864,22.605 60.864,30.395 60.864,53.759 61.584,54.478 61.584,54.932 61.263,55.252 61.05,55.252 61.05,58.48 63.215,60.645 63.215,71.92 64.415,73.12 64.415,75.52 63.053,76.882 63.053,81.259 63.783,81.989 63.783,83.724 62.54,84.967 62.54,97.115 v1(61.027,98.627)
UC_SYS_CAN_RX: J202.71 U206.4 | length 37.8
  Signal Layer 5 w0.3: v1(64.468,103.09) 68.1,99.458 68.1,94.015 67.205,93.12 67.205,92.482 67.205,69.217 68.102,68.32 v1(68.86,68.32)
UC_SYS_CAN_TX: J202.82 U206.1 | length 28.1
  Signal Layer 4 w0.3: v1(61.64,72.37) 61.64,73.183 61.637,73.18 61.637,76.961 63.053,78.378 63.053,80.873 63.053,82.145 62.65,82.548 62.65,83.135 62.65,93.08 62.65,97.857 v1(63.42,98.627)
  Bottom Layer w0.3: v1(63.42,98.627) 63.695,98.902 U206.1@63.695,99.28
UC_SYS_PLS_LOP: J202.106 Q208.1 R248.1 | length 71.4
  Signal Layer 5 w0.3: v1(41.79,134.08) 43.25,132.62 54.42,132.62 59.05,127.99 59.05,108.628 59.753,107.925 59.753,101.876 59.753,101.423 59.753,98.987 62.65,96.09 62.65,82.795 v1(61.73,81.875)
  Bottom Layer w0.3: Q208.1@40.09,136.45 40.11,136.47 40.91,136.47 41.79,135.59 R248.1@41.79,134.63 v1(41.79,134.08)
UC_SYS_PMBUS_SCL: D201.3 J202.87 R254.1 R255.2 | length 91.4
  Top Layer w0.3: v4(54.21,6.24) 55.25,7.28 57.9,7.28 58.49,6.69 67.26,6.69 72.473,11.903 72.473,61.756 71.2,63.029 71.2,66.546 69.93,67.816 69.93,72.264 70.707,73.04 D201.3@71.67,73.04 71.67,73.55 71.415,73.805 71.415,74.36 ; J202.87@67,74.72 70.339,74.72 R255.2@70.791,74.268 70.883,74.36 71.415,74.36 ; R254.1@72.14,74.36 71.415,74.36
UC_SYS_PMBUS_SDA: D201.6 J202.85 R249.2 R252.1 | length 90.5
  Top Layer w0.3: v4(56.21,6.24) 67.9,6.24 73.25,11.59 73.25,66.44 v1(72.08,66.44) 72.08,67.016 72.92,67.856 R249.2@72.92,68.19 72.92,69.28 R252.1@72.98,69.34 ; R252.1@72.97,69.34 D201.6@72.97,71.14
  Signal Layer 6 w0.3: v1(68.83,73.92) 71.15,73.92 72.08,72.99 v1(72.08,66.44)
UC_SYS_Present_L: J203.178 R427.1 | length 8.6
  Bottom Layer w0.3: v1@62.26,130.93 62.26,137.655 R427.1@63.575,138.97
  other v1: 62.29,130.81
UC_SYS_PS_KILL: J202.88 R416.1 | length 9.7
  Bottom Layer w0.3: R416.1@60.3,82.21 61.515,80.995 61.515,80.231 62.5,79.247 62.5,79.136 62.564,79.136 62.766,78.934 62.766,77.686 62.379,77.298 62.379,75.668 62.379,74.977 62.769,74.586 63.188,74.586 63.341,74.74 v1(63.42,74.74)
UC_SYS_PULSE_MGMT_1: J202.81 R417.1 | length 3.2
  Bottom Layer w0.3: v1(68.841,72.326) 69.614,72.326 69.614,73.107 70.142,73.635 70.142,74.242 R417.1@70.36,74.46
  other v1: 69.719,73.107
UC_SYS_RS485_RX: J202.76 R263.1 U207.1 | length 41.2
  Top Layer w0.3: U207.1@67.83,99.267 68.805,99.267 ; v1(68.81,98.08) 68.805,98.085 68.805,99.267 ; R263.1@70.122,99.257 70.112,99.267 68.805,99.267
  Signal Layer 2 w0.3: v1(61.637,69.894) 62.187,70.445 62.187,72.143 62.187,72.597 62.187,76.993 58.69,80.49 58.69,86.055 59.87,87.235 59.87,94.752 62.595,97.476 68.81,97.476 v1(68.81,98.08)
UC_SYS_RS485_TX: J202.78 R262.1 U207.4 | length 42.3
  Top Layer w0.3: U207.4@67.83,103.077 67.83,103.49 v1(68.47,104.13) 69.11,104.77 71.15,104.77 71.3,104.62 71.3,104.1 R262.1@71.71,103.69
  Signal Layer 2 w0.3: v1(64.047,70.716) 64.211,70.716 64.72,71.225 64.72,80.962 70.17,86.412 70.17,99 68.47,100.7 v1(68.47,104.13)
UC_SYS_SHELF_ADDR_A0: J202.105 R414.1 | length 75.4
  Top Layer w0.3: R414.1@52.771,19.326 52.791,19.346 52.811,19.326 v1(53.873,19.326) ; J202.105@67,81.92 69.774,81.92 v1(69.82,81.875)
  Signal Layer 4 w0.3: v1(53.873,19.326) 54.403,19.326 69.957,34.88 69.957,43.245 69.957,59.64 69.957,68.379 71.468,69.89 71.468,72.487 71.468,81.207 70.801,81.875 v1(69.82,81.875)
UC_SYS_SHELF_ADDR_A1: J202.107 R425.1 | length 94.1
  Top Layer w0.3: R425.1@40.178,25.332 v1(40.178,26.432) ; J202.107@67,82.72 69.758,82.72 v1(69.805,82.672)
  Signal Layer 4 w0.3: v1(40.178,26.432) 42.862,26.432 50.564,18.73 54.44,18.73 70.405,34.695 70.405,67.875 70.68,68.15 70.68,68.41 71.915,69.645 71.915,75.91 71.915,76.182 71.915,81.695 70.893,82.717 69.849,82.717 v1(69.805,82.672)
UC_SYS_SHELF_ADDR_A2: J202.109 R440.1 | length 8
  Top Layer w0.3: J202.109@67,83.52 69.795,83.52 v1(69.805,83.51)
  Bottom Layer w0.3: v1(69.805,83.51) 69.614,83.701 69.614,86.594 70.36,87.34 R440.1@71.32,87.34
UC_SYS_SHELF_ADDR_A3: J203.127 R455.1 | length 51.5
  Signal Layer 3 w0.3: v1(68.844,110.814) 69.308,110.814 71.015,109.106 71.015,103.037 71.015,102.583 71.015,73.74 71.367,73.388 71.367,63.635 71.974,63.029 v1(72.473,63.029)
  Bottom Layer w0.3: R455.1@72.23,61.51 72.23,62.479 72.473,62.721 v1(72.473,63.029)
UC_SYS_SOH_CTL: J203.137 Q210.1 R259.1 | length 24.2
  Bottom Layer w0.3: 62.765,114.305 61.681,114.305 R259.1@61.259,114.726 60.96,114.726 60.403,115.284 60.403,117.867 60.84,118.305 63.55,118.305 64.703,117.152 64.703,114.498 63.972,113.767 63.972,113.17 63.972,112.73 65.889,110.814 67.534,110.814 68.1,111.38 68.1,111.595 68.293,111.788 68.293,111.872 68.614,112.193 68.698,112.193 69.042,112.537 69.042,114.608 v1(68.83,114.82)
UC_SYS_SOH_L: C232.2 J203.138 Q210.3 R258.1 R260.1 R261.2 | length 8.8
  Bottom Layer w0.3: C232.2@62.42,117.74 63.6,116.56 R261.2@63.6,116.42 63.525,116.345 63.525,114.95 ; R260.1@63.59,110.08 63.39,110.28 R258.1@63.39,113.12 63.525,113.255 63.525,114.82 63.525,114.95 ; v1(63.95,114.82) 63.655,114.82 63.525,114.95
UC_SYS_SYNC_START2_CTL: J202.108 Q209.1 R251.1 | length 18.6
  Top Layer w0.3: J202.108@63.6,82.72 64.587,82.72 64.85,82.983 64.85,89.55 64.126,90.274 v1(64.126,96.338)
  Bottom Layer w0.3: 61.535,97.765 62.293,97.765 62.753,97.305 62.753,96.728 R251.1@62.926,96.555 63.205,96.276 v1@64.173,96.276
UC_SYS_SYNC_START2_L: C230.2 J202.90 Q209.3 R250.1 R253.2 R256.2 | length 27
  Signal Layer 2 w0.3: v1(60.847,94.955) 60.847,86.857 59.15,85.16 59.15,80.975 62.926,77.199 v1(62.926,75.441)
  Bottom Layer w0.3: R253.2@60.847,92.27 60.847,97.283 Q209.3@61.005,97.44
UC_SYS_SYNC_START_CTL: J203.170 Q211.1 R266.1 | length 16.4
  Signal Layer 4 w0.3: v1(62.03,127.622) 65.16,130.752 65.16,139.64 65.575,140.055 v1(65.829,140.055)
  Bottom Layer w0.3: 64.66,140.54 65.742,140.54 ; R266.1@65.82,141.24 65.82,140.055 v1(65.829,140.055)
UC_SYS_SYNC_START_L: C234.2 J203.167 Q211.3 R265.1 R268.1 R269.2 | length 30.2
  Signal Layer 2 w0.3: v1(63.01,143.625) 65.025,143.625 72.26,136.39 72.26,129.008 70.072,126.82 v1(68.96,126.82)
  Bottom Layer w0.3: R268.1@60.11,142.99 61.11,142.99 61.13,143.01 R269.2@61.83,143.01 R265.1@63.01,143.01 ; v1(63.01,143.625) R265.1@63.01,142.95 63.121,142.839 C234.2@63.121,141.59 63.935,141.59 Q211.3@64.335,141.19
UC_TA100_CLK: J203.130 U401.6 | length 41.1
  Signal Layer 4 w0.3: v1(64.125,111.645) 64.413,111.645 66.503,111.645 66.503,127.385 66.503,134.443 68.514,136.454 v1(69.31,136.454)
  Bottom Layer w0.3: U401.6@64.196,126.24 64.196,129.14 69.31,134.253 v1(69.31,136.454)
UC_TA100_RESET: J203.143 R412.1 U401.2 | length 12.3
  Top Layer w0.3: v1(65.26,119.11) 65.9,118.47 65.9,117.308 65.988,117.22 J203.143@67,117.22
  Bottom Layer w0.3: v1(65.26,119.11) 65.325,119.11 65.325,120.799 U401.2@65.466,120.94 65.466,122.432 66.664,123.63 69.68,123.63 R412.1@70.35,124.3
UC_TA100_SIMO: J203.125 U401.5 | length 38
  Signal Layer 3 w0.3: v1(68.58,135.057) 68.58,128.537 67.331,127.288 67.331,110.372 67.683,110.02 v1(68.844,110.02)
  Bottom Layer w0.3: U401.5@62.926,126.24 62.926,129.077 68.55,134.701 v1@68.55,135.01
UC_TA100_SOMI: J202.77 U401.7 | length 84.2
  Signal Layer 4 w0.3: v1(68.8,70.716) 66.794,70.716 65.685,71.825 65.685,73.91 66.495,74.72 69.298,74.72 69.51,74.932 69.51,81.405 66.95,83.965 66.95,127.2 70.03,130.28 v1(70.03,135.614)
  Bottom Layer w0.3: U401.7@65.466,126.24 65.466,128.406 70.03,132.97 v1(70.03,135.614)
UC_TA100_STE: J203.131 R413.1 U401.1 | length 18.4
  Top Layer w0.3: v1(65.3,118.02) 65.3,113.22 66.1,112.42 J203.131@67,112.42
  Bottom Layer w0.3: v1(65.3,118.02) 65.995,118.02 66.28,118.305 66.736,118.761 U401.1@66.736,120.94 66.736,122.225 67.331,122.82 70.921,122.82 71.94,123.839 R413.1@71.94,124.3
UC_UC_VFB_CHG: J202.58
  other v1: 63.97,62.72
UC_VFB_DIR_AUX: J203.161 pad.1@9.21,27.04 | length 192.3
  Signal Layer 2 w0.3: v2(8.73,27.04) 6.504,27.04 2.12,31.424 2.12,125.633 10.707,134.22 17.33,134.22 25.743,142.633 62.515,142.633 62.596,142.633 62.598,142.63 63.422,142.63 63.424,142.633 64.752,142.633 66.98,140.404 66.98,126.369 v1(68.933,124.415)
UC_VFB_DIR_CHG: J203.155
VAUX: C404.1 D400.1 pad.2@10.11,19.4 Q403.1-2-3-4 RT400.1 U400.4 | length 16.1
  Top Layer w0.254: U400.4@4.355,17.71 4.355,20.417 Q403.1-2-3-4@5.117,21.178
  Bottom Layer w1: 2.36,21.48 2.36,31.49 RT400.1@3.98,33.11
VBAT: pad.1@17.24,43.76 R220.2 | length 40.7
  Signal Layer 5 w0.3: v2(17.72,43.76) 19.164,43.76 21.324,45.92 46.062,45.92 47.804,44.178 50.989,44.178 v1(54.069,41.097)
  Bottom Layer w0.3: v1@54.014,41.025 54.014,40.601 54.22,40.395 R220.2@54.97,40.395
Vbattery_DAC: J202.14 R271.2 | length 24.2
  Top Layer w0.3: R271.2@46.34,30.409 v1(47.2,30.409)
  Bottom Layer w0.3: v1(47.2,30.409) 47.525,30.084 55.02,30.084 57.035,32.099 57.035,35.245 57.15,35.36 58.717,36.927 58.717,40.158 60.496,41.936 v1(61.759,41.936)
